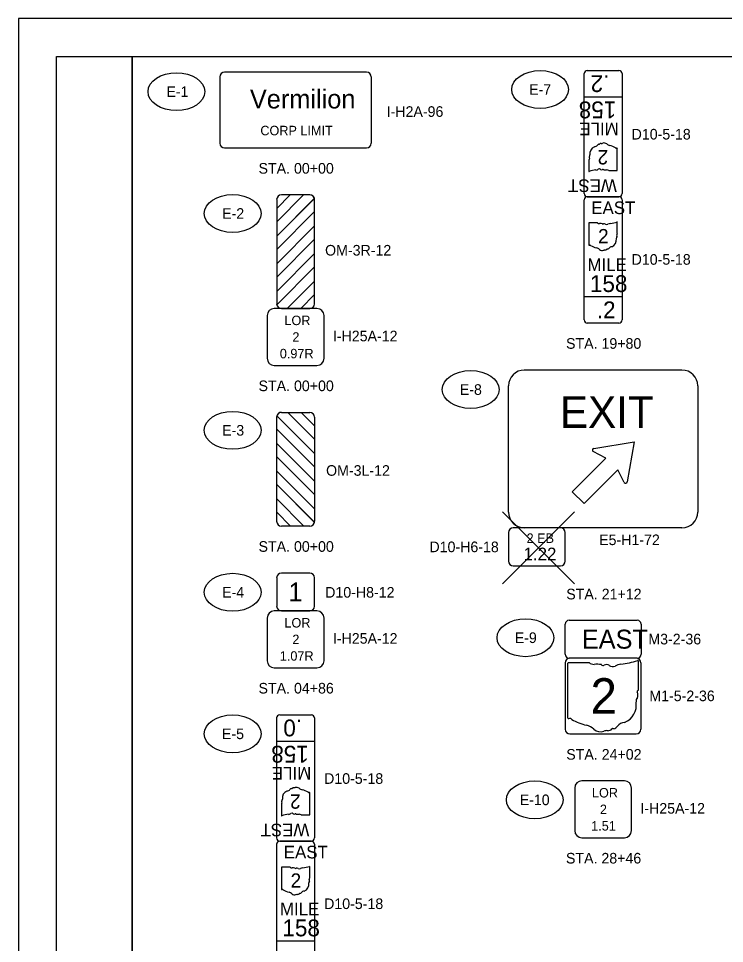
# Model space of a CAD drawing. Extents: x 0 to 34, y 0 to 22.
# Drawn here: x 0 to 9.32, y 9.79 to 22 of the extents above; entities that cross this region are included whole.
import ezdxf

# ---------------------------------------------------------------- set-up
doc = ezdxf.new("R2010")
doc.units = 0
for name, color, linetype in [('SH_Border', 7, 'Continuous'), ('SH_Cut_Line', 7, 'Continuous'), ('SH_Text', 7, 'Continuous'), ('SN_P_Signs', 7, 'Continuous'), ('SN_X_Public', 7, 'Continuous')]:
    doc.layers.add(name, color=color, linetype=linetype)

msp = doc.modelspace()

# ---------------------------------------------------------------- linework, layer by layer
at = {"layer": 'SH_Border'}
for points in [[(0.5, 21.5), (1.5, 21.5), (1.5, 0.5), (0.5, 0.5)], [(1.5, 21.5), (33.5, 21.5), (33.5, 0.5), (1.5, 0.5)]]:
    msp.add_lwpolyline(points, close=True, dxfattribs=at)
at = {"layer": 'SH_Cut_Line'}
msp.add_lwpolyline([(0, 0), (34, 0), (34, 22), (0, 22)], close=True, dxfattribs=at)
at = {"layer": 'SH_Text'}
for centre in [(2.086, 21.035), (6.889, 21.063), (2.829, 19.427), (5.971, 17.104), (2.829, 16.566), (2.829, 14.429), (6.695, 13.829), (2.829, 12.561), (6.818, 11.69)]:
    msp.add_ellipse(centre, major_axis=(0.375, 0), ratio=0.666667, dxfattribs=at)
at = {"layer": 'SN_P_Signs'}
for p, q in [((7.471, 20.968), (7.971, 20.968)), ((7.908, 19.998), (7.908, 20.283)), ((7.721, 20.169), (7.721, 20.169)), ((7.533, 20.135), (7.533, 19.986)), ((7.533, 20.135), (7.533, 20.135)), ((7.795, 19.993), (7.904, 19.993)), ((3.41, 19.318), (3.765, 19.673)), ((3.41, 19.494), (3.588, 19.673)), ((3.41, 19.129), (3.91, 19.629)), ((3.41, 18.952), (3.91, 19.452)), ((7.533, 19.298), (7.533, 19.014)), ((7.647, 19.303), (7.537, 19.303)), ((7.908, 19.161), (7.908, 19.31)), ((3.41, 18.763), (3.91, 19.263)), ((3.41, 18.587), (3.91, 19.087)), ((7.721, 19.127), (7.721, 19.127)), ((7.908, 19.161), (7.908, 19.161)), ((3.41, 18.398), (3.91, 18.898)), ((3.41, 18.221), (3.91, 18.721)), ((3.55, 18.173), (3.91, 18.532)), ((3.727, 18.173), (3.91, 18.356)), ((7.971, 18.329), (7.471, 18.329)), ((3.91, 16.259), (3.41, 16.759)), ((3.91, 16.448), (3.555, 16.803)), ((3.91, 16.624), (3.731, 16.803)), ((3.91, 16.082), (3.41, 16.582)), ((3.91, 15.893), (3.41, 16.393)), ((7.598, 16.326), (8.129, 16.416)), ((7.756, 16.2), (7.591, 16.287)), ((3.91, 15.717), (3.41, 16.217)), ((7.312, 15.756), (7.756, 16.2)), ((3.91, 15.528), (3.41, 16.028)), ((7.913, 16.043), (7.469, 15.599)), ((8, 15.878), (7.913, 16.043)), ((8, 15.878), (8, 15.878)), ((3.91, 15.351), (3.41, 15.851)), ((7.469, 15.599), (7.312, 15.756)), ((3.769, 15.303), (3.41, 15.662)), ((3.593, 15.303), (3.41, 15.486)), ((7.271, 14.06), (8.171, 14.06)), ((7.221, 13.61), (7.221, 14.01)), ((8.221, 14.01), (8.221, 13.61)), ((8.171, 13.56), (7.271, 13.56)), ((7.251, 13.488), (7.251, 12.776)), ((7.535, 13.5), (7.26, 13.5)), ((8.189, 13.145), (8.189, 13.518)), ((8.189, 13.146), (8.189, 13.145)), ((3.41, 12.465), (3.91, 12.465)), ((3.847, 11.496), (3.847, 11.781)), ((3.472, 11.633), (3.472, 11.484)), ((3.472, 11.633), (3.472, 11.633)), ((3.66, 11.667), (3.66, 11.667)), ((3.734, 11.491), (3.843, 11.491)), ((3.472, 10.796), (3.472, 10.511)), ((3.586, 10.801), (3.476, 10.801)), ((3.847, 10.659), (3.847, 10.808)), ((3.66, 10.625), (3.66, 10.625)), ((3.847, 10.659), (3.847, 10.659)), ((3.91, 9.827), (3.41, 9.827))]:
    msp.add_line(p, q, dxfattribs=at)
for points in [[(4.597, 21.293), (2.722, 21.293)], [(7.471, 19.69), (7.471, 21.273)], [(7.512, 21.315), (7.929, 21.315)], [(7.971, 21.273), (7.971, 19.69)], [(2.66, 21.23), (2.66, 20.355)], [(4.66, 20.355), (4.66, 21.23)], [(2.722, 20.293), (4.597, 20.293)], [(3.41, 19.61), (3.41, 19.494), (3.588, 19.673)], [(3.847, 19.673), (3.765, 19.673), (3.41, 19.318), (3.41, 19.129), (3.907, 19.627)], [(3.847, 19.673), (3.472, 19.673)], [(3.588, 19.673), (3.472, 19.673)], [(3.41, 19.61), (3.41, 18.235)], [(3.91, 18.235), (3.91, 19.61)], [(7.471, 18.023), (7.471, 19.607)], [(7.929, 19.648), (7.512, 19.648)], [(7.512, 19.648), (7.929, 19.648)], [(7.971, 19.607), (7.971, 18.023)], [(3.91, 19.263), (3.91, 19.452), (3.41, 18.952), (3.41, 18.763), (3.91, 19.263)], [(3.91, 18.898), (3.91, 19.087), (3.41, 18.587), (3.41, 18.398), (3.91, 18.898)], [(3.472, 18.173), (3.55, 18.173), (3.91, 18.532), (3.91, 18.721), (3.411, 18.222)], [(3.91, 18.235), (3.91, 18.356), (3.727, 18.173)], [(3.285, 18.079), (3.285, 17.516)], [(3.941, 18.173), (3.378, 18.173)], [(3.472, 18.173), (3.847, 18.173)], [(3.727, 18.173), (3.847, 18.173)], [(4.035, 17.516), (4.035, 18.079)], [(7.929, 17.982), (7.512, 17.982)], [(3.378, 17.423), (3.941, 17.423)], [(6.679, 17.362), (8.762, 17.362)], [(6.471, 15.487), (6.471, 17.153)], [(8.971, 17.153), (8.971, 15.487)], [(3.41, 15.365), (3.41, 16.74)], [(3.472, 16.803), (3.555, 16.803), (3.91, 16.448), (3.91, 16.259), (3.412, 16.757)], [(3.472, 16.803), (3.847, 16.803)], [(3.731, 16.803), (3.847, 16.803)], [(3.91, 16.74), (3.91, 16.624), (3.731, 16.803)], [(3.91, 16.74), (3.91, 15.365)], [(3.41, 16.393), (3.41, 16.582), (3.91, 16.082), (3.91, 15.893), (3.41, 16.393)], [(8.129, 16.416), (8.129, 16.416), (8.039, 15.884)], [(3.41, 16.028), (3.41, 16.217), (3.91, 15.717), (3.91, 15.528), (3.41, 16.028)], [(3.847, 15.303), (3.769, 15.303), (3.41, 15.662), (3.41, 15.851), (3.908, 15.352)], [(3.41, 15.365), (3.41, 15.486), (3.593, 15.303)], [(3.847, 15.303), (3.472, 15.303)], [(3.593, 15.303), (3.472, 15.303)], [(7.158, 15.278), (6.533, 15.278)], [(8.762, 15.278), (6.679, 15.278)], [(6.471, 15.216), (6.471, 14.841)], [(7.221, 14.841), (7.221, 15.216)], [(6.533, 14.778), (7.158, 14.778)], [(3.847, 14.683), (3.472, 14.683)], [(3.41, 14.62), (3.41, 14.245)], [(3.91, 14.245), (3.91, 14.62)], [(3.941, 14.183), (3.378, 14.183)], [(3.472, 14.183), (3.847, 14.183)], [(3.285, 14.089), (3.285, 13.526)], [(4.035, 13.526), (4.035, 14.089)], [(8.158, 13.56), (7.283, 13.56)], [(3.378, 13.433), (3.941, 13.433)], [(7.221, 13.497), (7.221, 12.622)], [(8.221, 12.622), (8.221, 13.497)], [(3.41, 11.188), (3.41, 12.771)], [(3.451, 12.813), (3.868, 12.813)], [(3.91, 12.771), (3.91, 11.188)], [(7.283, 12.56), (8.158, 12.56)], [(7.346, 11.846), (7.346, 11.284)], [(8.002, 11.94), (7.439, 11.94)], [(8.096, 11.284), (8.096, 11.846)], [(3.868, 11.146), (3.451, 11.146)], [(3.451, 11.146), (3.868, 11.146)], [(7.439, 11.19), (8.002, 11.19)], [(3.41, 9.521), (3.41, 11.104)], [(3.91, 11.104), (3.91, 9.521)]]:
    msp.add_lwpolyline(points, dxfattribs=at)
for centre, radius, start, end in [((2.722, 21.23), 0.0625, 90, 180), ((4.597, 21.23), 0.0625, 0, 90), ((7.512, 21.273), 0.0417, 90, 180), ((7.929, 21.273), 0.0417, 0, 90), ((2.722, 20.355), 0.0625, 180, 270), ((4.597, 20.355), 0.0625, 270, 0), ((7.644, 20.216), 0.0995, 112.3089, 188.9858), ((7.602, 20.363), 0.0545, 274.4031, 322.5768), ((7.671, 20.31), 0.0321, 102.8732, 143.2771), ((7.668, 20.35), 0.00855, 245.7517, 312.6484), ((7.695, 20.322), 0.0304, 88.777, 135.5493), ((7.699, 20.399), 0.0468, 265.6951, 291.2099), ((7.732, 20.301), 0.057, 50.7004, 106.2918), ((7.83, 20.411), 0.0899, 227.1842, 255.836), ((7.744, 20.044), 0.287, 60.4129, 77.1985), ((7.896, 20.299), 0.0121, 209.7484, 273.2717), ((7.903, 20.254), 0.0334, 87.339, 100.6039), ((7.904, 20.283), 0.00438, 351.9584, 78.3066), ((7.538, 20.136), 0.00447, 109.6038, 187.7341), ((7.575, 20.165), 0.0388, 160.033, 203.6496), ((7.534, 20.146), 0.00646, 287.944, 30.337), ((7.518, 20.197), 0.0282, 316.8065, 6.9296), ((7.537, 19.986), 0.00417, 171.8621, 277.738), ((7.667, 19.605), 0.398, 95.8445, 108.9065), ((7.616, 20.08), 0.08, 277.3462, 300.7689), ((7.67, 19.984), 0.0304, 53.8562, 114.8282), ((7.702, 20.029), 0.0253, 234.4667, 299.1411), ((7.72, 19.996), 0.0122, 39.7921, 117.1024), ((7.754, 20.153), 0.151, 260.4867, 274.9883), ((7.768, 19.96), 0.0421, 51.6195, 91.1119), ((7.904, 19.998), 0.00434, 278.1301, 8.1301), ((3.472, 19.61), 0.0625, 90, 180), ((3.472, 19.61), 0.0625, 90, 180), ((3.847, 19.61), 0.0625, 0, 90), ((3.847, 19.61), 0.0625, 15.2763, 90), ((7.512, 19.69), 0.0417, 180, 270), ((7.929, 19.69), 0.0417, 270, 360), ((7.512, 19.607), 0.0417, 90, 180), ((7.929, 19.607), 0.0417, 0, 90), ((7.537, 19.299), 0.00434, 98.1301, 188.1301), ((7.673, 19.336), 0.0421, 231.6195, 271.1119), ((7.687, 19.143), 0.151, 80.4867, 94.9883), ((7.721, 19.3), 0.0122, 219.7921, 297.1024), ((7.739, 19.267), 0.0253, 54.4667, 119.1411), ((7.772, 19.312), 0.0304, 233.8562, 294.8282), ((7.825, 19.216), 0.08, 97.3462, 120.7689), ((7.775, 19.691), 0.398, 275.8445, 288.9065), ((7.904, 19.311), 0.00417, 351.8621, 97.738), ((7.797, 19.08), 0.0995, 292.3089, 8.9858), ((7.923, 19.099), 0.0282, 136.8065, 186.9296), ((7.907, 19.15), 0.00646, 107.944, 210.337), ((7.866, 19.131), 0.0388, 340.033, 23.6496), ((7.904, 19.161), 0.00447, 289.6038, 7.7341), ((7.537, 19.013), 0.00438, 171.9584, 258.3066), ((7.538, 19.042), 0.0334, 267.339, 280.6039), ((7.545, 18.997), 0.0121, 29.7484, 93.2717), ((7.697, 19.253), 0.287, 240.4129, 257.1985), ((7.612, 18.886), 0.0899, 47.1842, 75.836), ((7.709, 18.996), 0.057, 230.7004, 286.2918), ((7.742, 18.897), 0.0468, 85.6951, 111.2099), ((7.746, 18.974), 0.0304, 268.777, 315.5493), ((7.773, 18.947), 0.00855, 65.7517, 132.6484), ((7.77, 18.986), 0.0321, 282.8732, 323.2771), ((7.839, 18.934), 0.0545, 94.4031, 142.5768), ((3.472, 18.235), 0.0625, 180, 270), ((3.472, 18.235), 0.0625, 191.732, 270), ((3.847, 18.235), 0.0625, 270, 0), ((3.847, 18.235), 0.0625, 270, 0), ((3.378, 18.079), 0.0938, 90, 180), ((3.941, 18.079), 0.0938, 0, 90), ((7.512, 18.023), 0.0417, 180, 270), ((7.929, 18.023), 0.0417, 270, 0), ((3.378, 17.516), 0.0938, 180, 270), ((3.941, 17.516), 0.0938, 270, 0), ((6.679, 17.153), 0.208, 90, 180), ((8.762, 17.153), 0.208, 0, 90), ((3.472, 16.74), 0.0625, 90, 180), ((3.472, 16.74), 0.0625, 90, 164.7237), ((3.847, 16.74), 0.0625, 0, 90), ((3.847, 16.74), 0.0625, 0, 90), ((7.601, 16.305), 0.0208, 99.6076, 242.1805), ((8.019, 15.888), 0.0208, 207.8195, 350.3924), ((6.679, 15.487), 0.208, 180, 270), ((8.762, 15.487), 0.208, 270, 0), ((3.472, 15.365), 0.0625, 180, 270), ((3.472, 15.365), 0.0625, 180, 270), ((3.847, 15.365), 0.0625, 270, 360), ((3.847, 15.365), 0.0625, 270, 348.268), ((6.533, 15.216), 0.0625, 90, 180), ((7.158, 15.216), 0.0625, 0, 90), ((6.533, 14.841), 0.0625, 180, 270), ((7.158, 14.841), 0.0625, 270, 0), ((3.472, 14.62), 0.0625, 90, 180), ((3.847, 14.62), 0.0625, 0, 90), ((3.378, 14.089), 0.0938, 90, 180), ((3.472, 14.245), 0.0625, 180, 270), ((3.847, 14.245), 0.0625, 270, 0), ((3.941, 14.089), 0.0938, 0, 90), ((7.271, 14.01), 0.05, 90, 180), ((8.171, 14.01), 0.05, 0, 90), ((7.271, 13.61), 0.05, 180, 270), ((7.283, 13.497), 0.0625, 90, 180), ((8.158, 13.497), 0.0625, 0, 90), ((8.171, 13.61), 0.05, 270, 0), ((3.378, 13.526), 0.0938, 180, 270), ((3.941, 13.526), 0.0938, 270, 0), ((7.262, 13.489), 0.0109, 98.1301, 188.1301), ((7.6, 13.583), 0.105, 231.6195, 271.1119), ((7.635, 13.101), 0.378, 80.4867, 94.9883), ((7.721, 13.493), 0.0304, 219.7921, 297.1024), ((7.766, 13.411), 0.0632, 54.4667, 119.1411), ((7.847, 13.524), 0.076, 233.8562, 294.8282), ((7.981, 13.283), 0.2, 97.3462, 120.7689), ((7.855, 14.47), 0.994, 275.8445, 288.9065), ((8.178, 13.519), 0.0104, 351.8621, 97.738), ((8.186, 13.118), 0.0162, 107.944, 210.337), ((8.083, 13.071), 0.097, 340.033, 23.6496), ((8.177, 13.144), 0.0112, 289.6038, 7.7341), ((7.91, 12.942), 0.249, 292.3089, 8.9858), ((8.226, 12.99), 0.0705, 136.8065, 186.9296), ((3.451, 12.771), 0.0417, 90, 180), ((3.868, 12.771), 0.0417, 0, 90), ((7.262, 12.775), 0.011, 171.9584, 258.3066), ((7.264, 12.848), 0.0836, 267.339, 280.6039), ((7.281, 12.735), 0.0302, 29.7484, 93.2717), ((7.661, 13.375), 0.718, 240.4129, 257.1985), ((8.015, 12.577), 0.136, 94.4031, 142.5768), ((7.283, 12.622), 0.0625, 180, 270), ((7.447, 12.457), 0.225, 47.1842, 75.836), ((7.69, 12.732), 0.143, 230.7004, 286.2918), ((7.773, 12.486), 0.117, 85.6951, 111.2099), ((7.783, 12.678), 0.0759, 268.777, 315.5493), ((7.852, 12.609), 0.0214, 65.7517, 132.6484), ((7.843, 12.707), 0.0803, 282.8732, 323.2771), ((8.158, 12.622), 0.0625, 270, 0), ((3.611, 11.808), 0.0321, 102.8732, 143.2771), ((3.607, 11.847), 0.00855, 245.7517, 312.6484), ((3.634, 11.82), 0.0304, 88.777, 135.5493), ((3.639, 11.897), 0.0468, 265.6951, 291.2099), ((3.671, 11.798), 0.057, 50.7004, 106.2918), ((3.769, 11.909), 0.0899, 227.1842, 255.836), ((7.439, 11.846), 0.0938, 90, 180), ((8.002, 11.846), 0.0938, 0, 90), ((3.583, 11.714), 0.0995, 112.3089, 188.9858), ((3.542, 11.861), 0.0545, 274.4031, 322.5768), ((3.683, 11.541), 0.287, 60.4129, 77.1985), ((3.835, 11.797), 0.0121, 209.7484, 273.2717), ((3.842, 11.752), 0.0334, 87.339, 100.6039), ((3.843, 11.781), 0.00438, 351.9584, 78.3066), ((3.477, 11.634), 0.00447, 109.6038, 187.7341), ((3.514, 11.663), 0.0388, 160.033, 203.6496), ((3.473, 11.644), 0.00646, 287.944, 30.337), ((3.457, 11.695), 0.0282, 316.8065, 6.9296), ((3.476, 11.483), 0.00417, 171.8621, 277.738), ((3.606, 11.103), 0.398, 95.8445, 108.9065), ((3.555, 11.578), 0.08, 277.3462, 300.7689), ((3.609, 11.482), 0.0304, 53.8562, 114.8282), ((3.641, 11.527), 0.0253, 234.4667, 299.1411), ((3.659, 11.494), 0.0122, 39.7921, 117.1024), ((3.694, 11.651), 0.151, 260.4867, 274.9883), ((3.708, 11.458), 0.0421, 51.6195, 91.1119), ((3.843, 11.495), 0.00434, 278.1301, 8.1301), ((7.439, 11.284), 0.0938, 180, 270), ((8.002, 11.284), 0.0938, 270, 0), ((3.451, 11.188), 0.0417, 180, 270), ((3.451, 11.104), 0.0417, 90, 180), ((3.868, 11.188), 0.0417, 270, 360), ((3.868, 11.104), 0.0417, 0, 90), ((3.477, 10.797), 0.00434, 98.1301, 188.1301), ((3.612, 10.834), 0.0421, 231.6195, 271.1119), ((3.626, 10.641), 0.151, 80.4867, 94.9883), ((3.66, 10.798), 0.0122, 219.7921, 297.1024), ((3.678, 10.765), 0.0253, 54.4667, 119.1411), ((3.711, 10.81), 0.0304, 233.8562, 294.8282), ((3.764, 10.714), 0.08, 97.3462, 120.7689), ((3.714, 11.189), 0.398, 275.8445, 288.9065), ((3.843, 10.809), 0.00417, 351.8621, 97.738), ((3.846, 10.648), 0.00646, 107.944, 210.337), ((3.805, 10.629), 0.0388, 340.033, 23.6496), ((3.843, 10.658), 0.00447, 289.6038, 7.7341), ((3.477, 10.511), 0.00438, 171.9584, 258.3066), ((3.477, 10.54), 0.0334, 267.339, 280.6039), ((3.484, 10.495), 0.0121, 29.7484, 93.2717), ((3.636, 10.751), 0.287, 240.4129, 257.1985), ((3.736, 10.578), 0.0995, 292.3089, 8.9858), ((3.862, 10.597), 0.0282, 136.8065, 186.9296), ((3.551, 10.383), 0.0899, 47.1842, 75.836), ((3.648, 10.494), 0.057, 230.7004, 286.2918), ((3.681, 10.395), 0.0468, 85.6951, 111.2099), ((3.685, 10.472), 0.0304, 268.777, 315.5493), ((3.712, 10.445), 0.00855, 65.7517, 132.6484), ((3.709, 10.484), 0.0321, 282.8732, 323.2771), ((3.778, 10.431), 0.0545, 94.4031, 142.5768)]:
    msp.add_arc(centre, radius, start, end, dxfattribs=at)
at = {"layer": 'SN_X_Public'}
for p, q in [((6.393, 14.542), (7.343, 15.492)), ((6.393, 15.492), (7.343, 14.542))]:
    msp.add_line(p, q, dxfattribs=at)

# ---------------------------------------------------------------- texts
at = {"layer": 'SH_Text'}
for s, p in [('E-7', (6.743, 20.993)), ('E-1', (1.953, 20.965)), ('I-H2A-96', (4.862, 20.702)), ('D10-5-18', (8.097, 20.403)), ('STA. 00+00', (3.17, 19.953)), ('E-2', (2.689, 19.357)), ('OM-3R-12', (4.049, 18.872)), ('D10-5-18', (8.097, 18.751)), ('I-H25A-12', (4.152, 17.74)), ('STA. 19+80', (7.231, 17.642)), ('STA. 00+00', (3.17, 17.083)), ('E-8', (5.828, 17.034)), ('E-3', (2.689, 16.496)), ('OM-3L-12', (4.062, 15.966)), ('E5-H1-72', (7.668, 15.051)), ('STA. 00+00', (3.17, 14.963)), ('D10-H6-18', (5.427, 14.958)), ('E-4', (2.689, 14.359)), ('D10-H8-12', (4.05, 14.358)), ('STA. 21+12', (7.234, 14.335)), ('I-H25A-12', (4.152, 13.75)), ('E-9', (6.553, 13.759)), ('M3-2-36', (8.318, 13.741)), ('STA. 04+86', (3.17, 13.093)), ('M1-5-2-36', (8.331, 12.992)), ('E-5', (2.687, 12.491)), ('STA. 24+02', (7.234, 12.22)), ('D10-5-18', (4.036, 11.901)), ('E-10', (6.619, 11.62)), ('I-H25A-12', (8.213, 11.508)), ('STA. 28+46', (7.23, 10.85)), ('D10-5-18', (4.036, 10.249))]:
    msp.add_text(s, height=0.14, dxfattribs=at).set_placement(p)
at = {"layer": 'SN_P_Signs'}
for s, height, p in [('.2', 0.2222, (7.804, 21.252)), ('158', 0.2222, (7.895, 20.905)), ('MILE', 0.1667, (7.927, 20.627)), ('2', 0.188, (7.787, 20.263)), ('WEST', 0.1667, (7.902, 19.877)), ('.0', 0.2222, (3.745, 12.75)), ('158', 0.2222, (3.834, 12.403)), ('MILE', 0.1667, (3.866, 12.125)), ('2', 0.188, (3.726, 11.761)), ('WEST', 0.1667, (3.841, 11.375))]:
    msp.add_text(s, height=height, rotation=180, dxfattribs=at).set_placement(p)
for s, height, p in [('Vermilion', 0.25, (3.056, 20.813)), ('CORP LIMIT', 0.125, (3.194, 20.459)), ('EAST', 0.1667, (7.564, 19.419)), ('2', 0.188, (7.654, 19.034)), ('MILE', 0.1667, (7.514, 18.669)), ('158', 0.2222, (7.546, 18.391)), ('.2', 0.2222, (7.637, 18.044)), ('LOR', 0.125, (3.512, 17.954)), ('2', 0.125, (3.617, 17.735)), ('0.97R', 0.125, (3.451, 17.516)), ('EXIT', 0.4167, (7.15, 16.598)), ('2 EB', 0.125, (6.71, 15.08)), ('1.22', 0.1667, (6.67, 14.851)), ('1', 0.25, (3.565, 14.308)), ('LOR', 0.125, (3.512, 13.964)), ('EAST', 0.25, (7.439, 13.685)), ('2', 0.125, (3.617, 13.745)), ('1.07R', 0.125, (3.451, 13.526)), ('2', 0.469, (7.554, 12.826)), ('LOR', 0.125, (7.573, 11.721)), ('2', 0.125, (7.678, 11.502)), ('1.51', 0.125, (7.563, 11.284)), ('EAST', 0.1667, (3.503, 10.917)), ('2', 0.188, (3.593, 10.531)), ('MILE', 0.1667, (3.453, 10.167)), ('158', 0.2222, (3.485, 9.889))]:
    msp.add_text(s, height=height, dxfattribs=at).set_placement(p)

doc.saveas('drawing.dxf')
